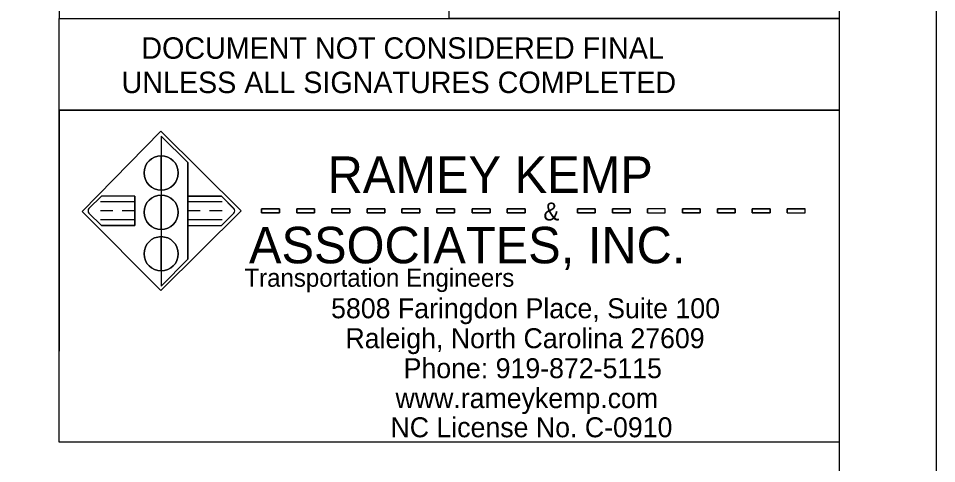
# Model space of a CAD drawing. Extents: x 573078 to 573117.1, y -55221.3 to -55199.3.
# Drawn here: x 573107.304 to 573112.014, y -55205.083 to -55202.8 of the extents above; entities that cross this region are included whole.
import ezdxf

# ---------------------------------------------------------------- set-up
doc = ezdxf.new("R2010")
doc.units = 0
for name, color, linetype in [('Old_Level_2', 7, 'Continuous'), ('Old_Level_4', 7, 'Continuous'), ('Sheet Plan CELL', 7, 'Continuous'), ('Sheet Plot Border Inside CELL', 7, 'Continuous'), ('Sheet Sticker Exception Certification CELL', 7, 'Continuous')]:
    doc.layers.add(name, color=color, linetype=linetype)

msp = doc.modelspace()

# ---------------------------------------------------------------- linework, layer by layer
at = {"layer": 'Old_Level_2'}
for p, q in [((573108.0362, -55203.4038), (573108.0362, -55204.1729)), ((573108.0362, -55203.4038), (573108.1731, -55203.5391)), ((573108.1731, -55203.5391), (573108.1731, -55204.0354)), ((573107.7299, -55203.7122), (573107.666, -55203.7751)), ((573107.9008, -55203.7122), (573107.7299, -55203.7122)), ((573107.9008, -55203.7122), (573107.9008, -55203.8622)), ((573108.1731, -55203.7123), (573108.3461, -55203.7123)), ((573108.3461, -55203.7123), (573108.409, -55203.7757)), ((573107.7299, -55203.8615), (573107.666, -55203.7985)), ((573108.3461, -55203.8615), (573108.409, -55203.7981)), ((573107.9008, -55203.8615), (573107.7299, -55203.8615)), ((573107.9008, -55203.8622), (573107.7299, -55203.8622)), ((573108.1731, -55203.8615), (573108.3461, -55203.8615)), ((573108.0362, -55204.1729), (573108.1731, -55204.0354))]:
    msp.add_line(p, q, dxfattribs=at)
for points in [[(573108.0362, -55204.095), (573108.0362, -55204.1729), (573108.1731, -55204.0354), (573108.1731, -55203.8333), (573108.1731, -55203.7871), (573108.1731, -55203.7414), (573108.1731, -55203.5391), (573108.0362, -55203.4038), (573108.0362, -55203.5043)], [(573108.0362, -55203.68), (573108.0362, -55203.5043)], [(573108.0362, -55203.68), (573108.0362, -55203.7061)], [(573107.9008, -55203.8333), (573107.9008, -55203.7871), (573107.9008, -55203.7414), (573107.9008, -55203.7122), (573107.7299, -55203.7122), (573107.666, -55203.7751)], [(573108.0362, -55203.8819), (573108.0362, -55203.7061)], [(573108.4087, -55203.7753), (573108.3461, -55203.7123), (573108.1731, -55203.7123), (573108.1731, -55203.7414), (573108.1731, -55203.7871), (573108.1731, -55203.8333)], [(573108.5514, -55203.7765), (573108.5514, -55203.7975), (573108.6429, -55203.7975), (573108.6429, -55203.7765), (573108.5514, -55203.7765)], [(573108.7328, -55203.7765), (573108.7328, -55203.7975), (573108.8227, -55203.7975), (573108.8227, -55203.7765), (573108.7328, -55203.7765)], [(573108.9124, -55203.7765), (573108.9124, -55203.7975), (573109.0033, -55203.7975), (573109.0033, -55203.7765), (573108.9124, -55203.7765)], [(573109.0924, -55203.7765), (573109.0924, -55203.7975), (573109.1832, -55203.7975), (573109.1832, -55203.7765), (573109.0924, -55203.7765)], [(573109.2715, -55203.7765), (573109.2715, -55203.7975), (573109.3625, -55203.7975), (573109.3625, -55203.7765), (573109.2715, -55203.7765)], [(573109.4506, -55203.7765), (573109.4506, -55203.7975), (573109.5416, -55203.7975), (573109.5416, -55203.7765), (573109.4506, -55203.7765)], [(573109.6319, -55203.7765), (573109.6319, -55203.7975), (573109.7232, -55203.7975), (573109.7232, -55203.7765), (573109.6319, -55203.7765)], [(573109.8116, -55203.7765), (573109.8116, -55203.7975), (573109.9027, -55203.7975), (573109.9027, -55203.7765), (573109.8116, -55203.7765)], [(573110.1721, -55203.7765), (573110.1721, -55203.7975), (573110.2628, -55203.7975), (573110.2628, -55203.7765), (573110.1721, -55203.7765)], [(573110.3512, -55203.7765), (573110.3512, -55203.7975), (573110.4421, -55203.7975), (573110.4421, -55203.7765), (573110.3512, -55203.7765)], [(573110.6215, -55203.7765), (573110.5305, -55203.7765), (573110.5305, -55203.7975), (573110.6215, -55203.7975), (573110.6215, -55203.7765)], [(573110.7099, -55203.7765), (573110.7099, -55203.7975), (573110.8009, -55203.7975), (573110.8009, -55203.7765), (573110.7099, -55203.7765)], [(573110.8893, -55203.7765), (573110.8893, -55203.7975), (573110.9803, -55203.7975), (573110.9803, -55203.7765), (573110.8893, -55203.7765)], [(573111.0687, -55203.7765), (573111.0687, -55203.7975), (573111.1597, -55203.7975), (573111.1597, -55203.7765), (573111.0687, -55203.7765)], [(573111.2481, -55203.7975), (573111.339, -55203.7975), (573111.339, -55203.7765), (573111.2481, -55203.7765), (573111.2481, -55203.7975)], [(573107.666, -55203.7985), (573107.7299, -55203.8622), (573107.9008, -55203.8622), (573107.9008, -55203.8333)], [(573108.1731, -55203.8333), (573108.1731, -55203.8615), (573108.3461, -55203.8615), (573108.4087, -55203.7985)], [(573108.0362, -55203.8819), (573108.0362, -55203.9192)], [(573108.0362, -55204.095), (573108.0362, -55203.9192)]]:
    msp.add_lwpolyline(points, dxfattribs=at)
for centre, radius, start, end in [((573108.0362, -55203.5922), 0.0879, 90, 180), ((573108.0362, -55203.5922), 0.0879, 0, 90), ((573108.0362, -55203.5922), 0.0879, 180, 270), ((573108.0362, -55203.5922), 0.0879, 270, 0), ((573108.0362, -55203.794), 0.0879, 90, 180), ((573108.0362, -55203.794), 0.0879, 0, 90), ((573107.6775, -55203.7868), 0.0164, 134.5812, 225.4188), ((573107.6775, -55203.7868), 0.0164, 134.5812, 225.4188), ((573108.3971, -55203.7869), 0.0164, 315.2131, 44.7869), ((573108.3971, -55203.7869), 0.0164, 315.2131, 44.7869), ((573108.0362, -55203.794), 0.0879, 180, 270), ((573108.0362, -55203.794), 0.0879, 270, 0), ((573108.0362, -55204.0071), 0.0879, 90, 180), ((573108.0362, -55204.0071), 0.0879, 0, 90), ((573108.0362, -55204.0071), 0.0879, 180, 270), ((573108.0362, -55204.0071), 0.0879, 270, 0)]:
    msp.add_arc(centre, radius, start, end, dxfattribs=at)
at = {"layer": 'Old_Level_4'}
for p, q in [((573108.0353, -55203.3787), (573107.6305, -55203.7894)), ((573108.0353, -55203.3787), (573108.446, -55203.7874)), ((573107.9008, -55203.7414), (573107.7257, -55203.7414)), ((573108.3485, -55203.7414), (573108.1735, -55203.7414)), ((573110.5305, -55203.7975), (573110.5305, -55203.7765)), ((573110.6215, -55203.7765), (573110.5305, -55203.7765)), ((573110.6215, -55203.7975), (573110.6215, -55203.7765)), ((573111.2481, -55203.7975), (573111.2481, -55203.7765)), ((573111.2481, -55203.7765), (573111.339, -55203.7765)), ((573111.339, -55203.7975), (573111.339, -55203.7765)), ((573108.0353, -55204.1962), (573107.6305, -55203.7894)), ((573107.789, -55203.7871), (573107.7257, -55203.7871)), ((573107.9008, -55203.7871), (573107.8369, -55203.7871)), ((573108.446, -55203.7874), (573108.0353, -55204.1962)), ((573108.2368, -55203.7871), (573108.1735, -55203.7871)), ((573108.3485, -55203.7871), (573108.2846, -55203.7871)), ((573110.5305, -55203.7975), (573110.6215, -55203.7975)), ((573111.2481, -55203.7975), (573111.339, -55203.7975)), ((573107.9008, -55203.8333), (573107.7257, -55203.8333)), ((573108.3485, -55203.8333), (573108.1735, -55203.8333))]:
    msp.add_line(p, q, dxfattribs=at)
for points in [[(573108.0353, -55203.3787), (573107.6305, -55203.7894), (573108.0353, -55204.1962), (573108.446, -55203.7874), (573108.0353, -55203.3787)], [(573108.0362, -55203.5043), (573108.0362, -55203.68)], [(573108.0362, -55203.7061), (573108.0362, -55203.8819)], [(573108.0362, -55203.9192), (573108.0362, -55204.095)]]:
    msp.add_lwpolyline(points, dxfattribs=at)
for points in [[(573108.5514, -55203.7765), (573108.6429, -55203.7765), (573108.6429, -55203.7975), (573108.5514, -55203.7975)], [(573108.7328, -55203.7765), (573108.8227, -55203.7765), (573108.8227, -55203.7975), (573108.7328, -55203.7975)], [(573108.9124, -55203.7765), (573109.0033, -55203.7765), (573109.0033, -55203.7975), (573108.9124, -55203.7975)], [(573109.0924, -55203.7765), (573109.1832, -55203.7765), (573109.1832, -55203.7975), (573109.0924, -55203.7975)], [(573109.2715, -55203.7765), (573109.3625, -55203.7765), (573109.3625, -55203.7975), (573109.2715, -55203.7975)], [(573109.4506, -55203.7765), (573109.5416, -55203.7765), (573109.5416, -55203.7975), (573109.4506, -55203.7975)], [(573109.6319, -55203.7765), (573109.7232, -55203.7765), (573109.7232, -55203.7975), (573109.6319, -55203.7975)], [(573109.8116, -55203.7765), (573109.9027, -55203.7765), (573109.9027, -55203.7975), (573109.8116, -55203.7975)], [(573110.1721, -55203.7765), (573110.2628, -55203.7765), (573110.2628, -55203.7975), (573110.1721, -55203.7975)], [(573110.3512, -55203.7765), (573110.4421, -55203.7765), (573110.4421, -55203.7975), (573110.3512, -55203.7975)], [(573110.7099, -55203.7765), (573110.8009, -55203.7765), (573110.8009, -55203.7975), (573110.7099, -55203.7975)], [(573110.8893, -55203.7765), (573110.9803, -55203.7765), (573110.9803, -55203.7975), (573110.8893, -55203.7975)], [(573111.0687, -55203.7765), (573111.1597, -55203.7765), (573111.1597, -55203.7975), (573111.0687, -55203.7975)]]:
    msp.add_lwpolyline(points, close=True, dxfattribs=at)
for centre in [(573108.0362, -55203.5922), (573108.0362, -55203.794), (573108.0362, -55204.0071)]:
    msp.add_circle(centre, 0.0879, dxfattribs=at)
for centre, start, end in [((573108.0362, -55203.5922), 0, 90), ((573108.0362, -55203.5922), 270, 0), ((573108.0362, -55203.794), 0, 90), ((573108.0362, -55203.794), 270, 0), ((573108.0362, -55204.0071), 0, 90), ((573108.0362, -55204.0071), 270, 0)]:
    msp.add_arc(centre, 0.0879, start, end, dxfattribs=at)
at = {"layer": 'Sheet Plan CELL'}
for q in [(573107.5132, -55202.7999), (573107.5132, -55204.5066)]:
    msp.add_line((573107.5132, -55203.2699), q, dxfattribs=at)
for points in [[(573081.5142, -55199.7984), (573111.5142, -55199.7984), (573111.5142, -55220.7984), (573081.5142, -55220.7984)], [(573109.5142, -55200.5499), (573107.5132, -55200.5499), (573107.5132, -55202.7999), (573109.5142, -55202.7999)], [(573109.5142, -55200.5499), (573111.5142, -55200.5499), (573111.5142, -55202.7999), (573109.5142, -55202.7999)], [(573111.5139, -55204.9735), (573107.5132, -55204.9735), (573107.5132, -55203.2699), (573111.5139, -55203.2699)]]:
    msp.add_lwpolyline(points, close=True, dxfattribs=at)
at = {"layer": 'Sheet Plot Border Inside CELL'}
msp.add_lwpolyline([(573112.0142, -55199.2984), (573078.0142, -55199.2984), (573078.0142, -55221.2984), (573112.0142, -55221.2984)], close=True, dxfattribs=at)
at = {"layer": 'Sheet Sticker Exception Certification CELL'}
for p, q in [((573107.5132, -55202.7999), (573111.5142, -55202.7999)), ((573111.5142, -55202.7999), (573111.5139, -55203.2702)), ((573111.5139, -55203.2699), (573107.5132, -55203.2699))]:
    msp.add_line(p, q, dxfattribs=at)

# ---------------------------------------------------------------- texts
at = {"layer": 'Old_Level_4'}
for s, height, p in [('RAMEY KEMP', 0.18711, (573108.89, -55203.6946)), ('&', 0.0919, (573109.9967, -55203.836)), ('ASSOCIATES, INC.', 0.187109, (573108.4867, -55204.056)), ('Transportation Engineers', 0.092176, (573108.4635, -55204.1762)), ('5808 Faringdon Place, Suite 100', 0.102418, (573108.908, -55204.3378)), ('Raleigh, North Carolina 27609', 0.102418, (573108.9816, -55204.4914)), ('Phone: 919-872-5115 ', 0.102418, (573109.28, -55204.6451)), ('www.rameykemp.com', 0.102418, (573109.2385, -55204.7987)), ('NC License No. C-0910', 0.102418, (573109.2125, -55204.9482))]:
    msp.add_text(s, height=height, dxfattribs=at).set_placement(p)
at = {"layer": 'Sheet Sticker Exception Certification CELL'}
for s, p in [('DOCUMENT NOT CONSIDERED FINAL', (573107.9346, -55203.0068)), ('UNLESS ALL SIGNATURES COMPLETED', (573107.8332, -55203.1828))]:
    msp.add_text(s, height=0.11, dxfattribs=at).set_placement(p)

doc.saveas('drawing.dxf')
